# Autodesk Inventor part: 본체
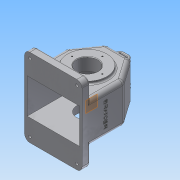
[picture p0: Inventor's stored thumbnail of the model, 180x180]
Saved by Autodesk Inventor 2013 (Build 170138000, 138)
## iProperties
Created: 2016-12
Part Number: 본체
Material: 알루미늄 6061
Document SubType Name: Modeling
Designer: Administrator
Density: 2.71 g/cm^3
Mass: 1062.36 g
Surface Area: 1145.91 cm^2
Volume: 392.016 cm^3
Author: Administrator
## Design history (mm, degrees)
sketch "스케치1"
  geometry: L1 (23.491, 60)-(-23.491, 60); L2 (-23.491, 60)-(-55, 15); L3 (-55, 15)-(-55, -65); L4 (-55, -65)-(55, -65); L5 (55, -65)-(55, 15); L6 (55, 15)-(23.491, 60); 2 further points
  constraints: 12 end point, 2 parallel, 1 horizontal, 1 midpoint, 1 perpendicular, 1 vertical alignment
  dimensions: "d0" = 125 distance between parallel lines of L4 L1; "d3" = 35 deg angle of L3 L2; "d4" = 35 deg angle of L6 L5; "d5" = 110 distance of L3.end L4.end; "d6" = 80 distance from line of L4 L5.end; "d7" = 80 distance of L3.end L2.end; "d8" = 65 distance from line of L4 point (0, 0)
extrude "돌출1" new body sketch "스케치1" stored distance "d9" = 77; taper "d10" = 0 deg
feature "쉘1" dims "d26" = 5
sketch "스케치2"
  geometry: C1 r 37.5 at (0, 0); 1 further point
  constraints: 1 centre point, 1 coincident
  dimensions: "d11" = 75 diameter of C1
extrude "돌출2" join sketch "스케치2" distance "d12" = 5; taper "d13" = 0 deg
sketch "스케치3"
  geometry: C1 r 31 at (0, 0); 1 further point
  constraints: 1 centre point, 1 coincident
  dimensions: "d14" = 62 diameter of C1
extrude "돌출3" join sketch "스케치3" distance "d15" = 10; taper "d16" = 0 deg
hole "구멍1" diameter "d19" = 40; stored, may be unused: countersink angle "d23" = 90 deg, drill point angle "d25" = 0 deg; dims "d17" = 10, "d18" = 10, "d20" = 6, "d21" = 4, "d22" = 2, "d24" = 15
node "작업 평면1"
sketch "스케치5"
  geometry: C1 r 27 at (0, 0); 1 further point
  constraints: 1 centre point, 1 coincident
  dimensions: "d29" = 54 diameter of C1
extrude "돌출4" join sketch "스케치5" distance "d30" = 24; taper "d31" = 0 deg
feature "면 기울기1" dims angle "d32" = -45 deg
hole "구멍2" diameter "d35" = 40; stored, may be unused: countersink angle "d39" = 90 deg, drill point angle "d41" = 0 deg; dims "d33" = 10, "d34" = 10, "d36" = 6, "d37" = 4, "d38" = 2, "d40" = 24
chamfer "모따기1" distance "d42" = 1; stored, may be unused: second distance "d43" = 2, angle "d44" = 45 deg
sketch "스케치6"
  geometry: C1 r 31 at (0, 0) reference; 1 further point
  constraints: 1 vertical alignment
  dimensions: "d45" = 26 distance of C1.centre point (0, 26)
hole "구멍3" sketch "스케치6" at (0, 26) diameter "d46" = 2.459; stored, may be unused: countersink angle "d50" = 90 deg, drill point angle "d52" = 118 deg; dims "d47" = 6, "d48" = 4, "d49" = 2, "d51" = 8
fillet "모깎기1" dims "d56" = 3
fillet "모깎기2" dims "d57" = 3
sketch "스케치7"
  geometry: C1 r 37.5 at (0, 0) reference; 1 further point
  constraints: 1 vertical alignment
  dimensions: "d58" = 29 distance of C1.centre point (0, 29)
hole "구멍4" sketch "스케치7" at (0, 29) diameter "d59" = 2.459; stored, may be unused: countersink angle "d63" = 90 deg, drill point angle "d65" = 118 deg; dims "d60" = 6, "d61" = 4, "d62" = 2, "d64" = 8
sketch "스케치8"
  geometry: L1 (110, -77)-(110, 0) reference; L2 (0, 0)-(110, 0) reference; L3 (0, -77)-(0, 0) reference; L4 (110, -77)-(0, -77) reference; L5 (0, 36.5)-(110, 36.5); L6 (110, 36.5)-(110, -113.5); L7 (110, -113.5)-(0, -113.5); L8 (0, -113.5)-(0, 36.5); L9 (0, 36.5)-(110, -113.5); L10 (110, 36.5)-(0, -113.5); 1 further point
  constraints: 12 end point, 2 midpoint, 2 parallel, 1 horizontal, 1 perpendicular
  dimensions: "d69" = 110 distance of L6.end L7.end; "d70" = 150 distance of L5.end L6.end
extrude "돌출5" join sketch "스케치8" distance "d71" = 15; taper "d72" = 0 deg
fillet "모깎기3" dims "d73" = 10
sketch "스케치9"
  geometry: 2 further points
  dimensions: "d74" = 45 horizontal distance of point (55, 38.5) point (10, 103.5); "d76" = 65 vertical distance of point (10, 103.5) point (55, 38.5)
hole "구멍5" sketch "스케치9" at (10, 103.5) diameter "d77" = 5; stored, may be unused: countersink angle "d81" = 90 deg, drill point angle "d83" = 118 deg; dims "d78" = 5, "d79" = 12, "d80" = 5, "d82" = 8
fillet "모깎기5" dims "d91" = 8
fillet "모깎기6" dims "d92" = 10
fillet "모깎기7" dims "d93" = 3
node "작업 평면3"
sketch "스케치10"
  geometry: L1 (95.5, -18)-(-34.5, -18) reference; 1 further point
  constraints: 1 other
  dimensions: "d113" = 45 distance from line of L1 point (30.5, 27)
feature "엠보싱1" sketch "스케치10" dims "d0" = 125, "d3" = 35 deg, "d4" = 35 deg, "d5" = 110, "d6" = 80, "d7" = 80, "d8" = 65, "d95" = 0.5, "d96" = 0
node "작업 평면2"
sketch "스케치12"
  geometry: L1 (-18.285, 60)-(18.285, 60) reference; L2 (-12.5, 60)-(-12.5, 75); L3 (-12.5, 75)-(12.5, 75); L4 (12.5, 75)-(12.5, 60); L5 (50, -65)-(-50, -65) reference; L6 (7.5, 60)-(7.5, 70); L7 (7.5, 70)-(-7.5, 70); L8 (-7.5, 70)-(-7.5, 60); L9 (-7.5, 60)-(-12.5, 60); L10 (7.5, 60)-(12.5, 60); 2 further points
  constraints: 16 end point, 4 perpendicular, 2 collinear, 2 point on line, 1 midpoint, 1 vertical alignment, 2 other
  dimensions: "d102" = 25 distance of L2.end L3.end; "d104" = 140 distance between parallel lines of L5 L3; "d105" = 15 distance of L6.end L7.end
extrude "돌출6" join sketch "스케치12" distance "d106" = 8; taper "d107" = 0 deg
fillet "모깎기10" dims "d110" = 8
fillet "모깎기11" dims "d111" = 1
fillet "모깎기12" dims "d112" = 1
fillet "모깎기13" dims "d114" = 3
node "솔리드1"
pattern_circular "원형 패턴1" dims angle "d54" = 360 deg
pattern_circular "원형 패턴2" dims angle "d67" = 360 deg
pattern_linear "직사각형 패턴1" dims "d86" = 90
mirror "대칭1"
other parameters: "d28" = -24, "d101" = 26
